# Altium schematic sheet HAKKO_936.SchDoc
size A3; DocumentNumber: 1/1; Revision: 1.0
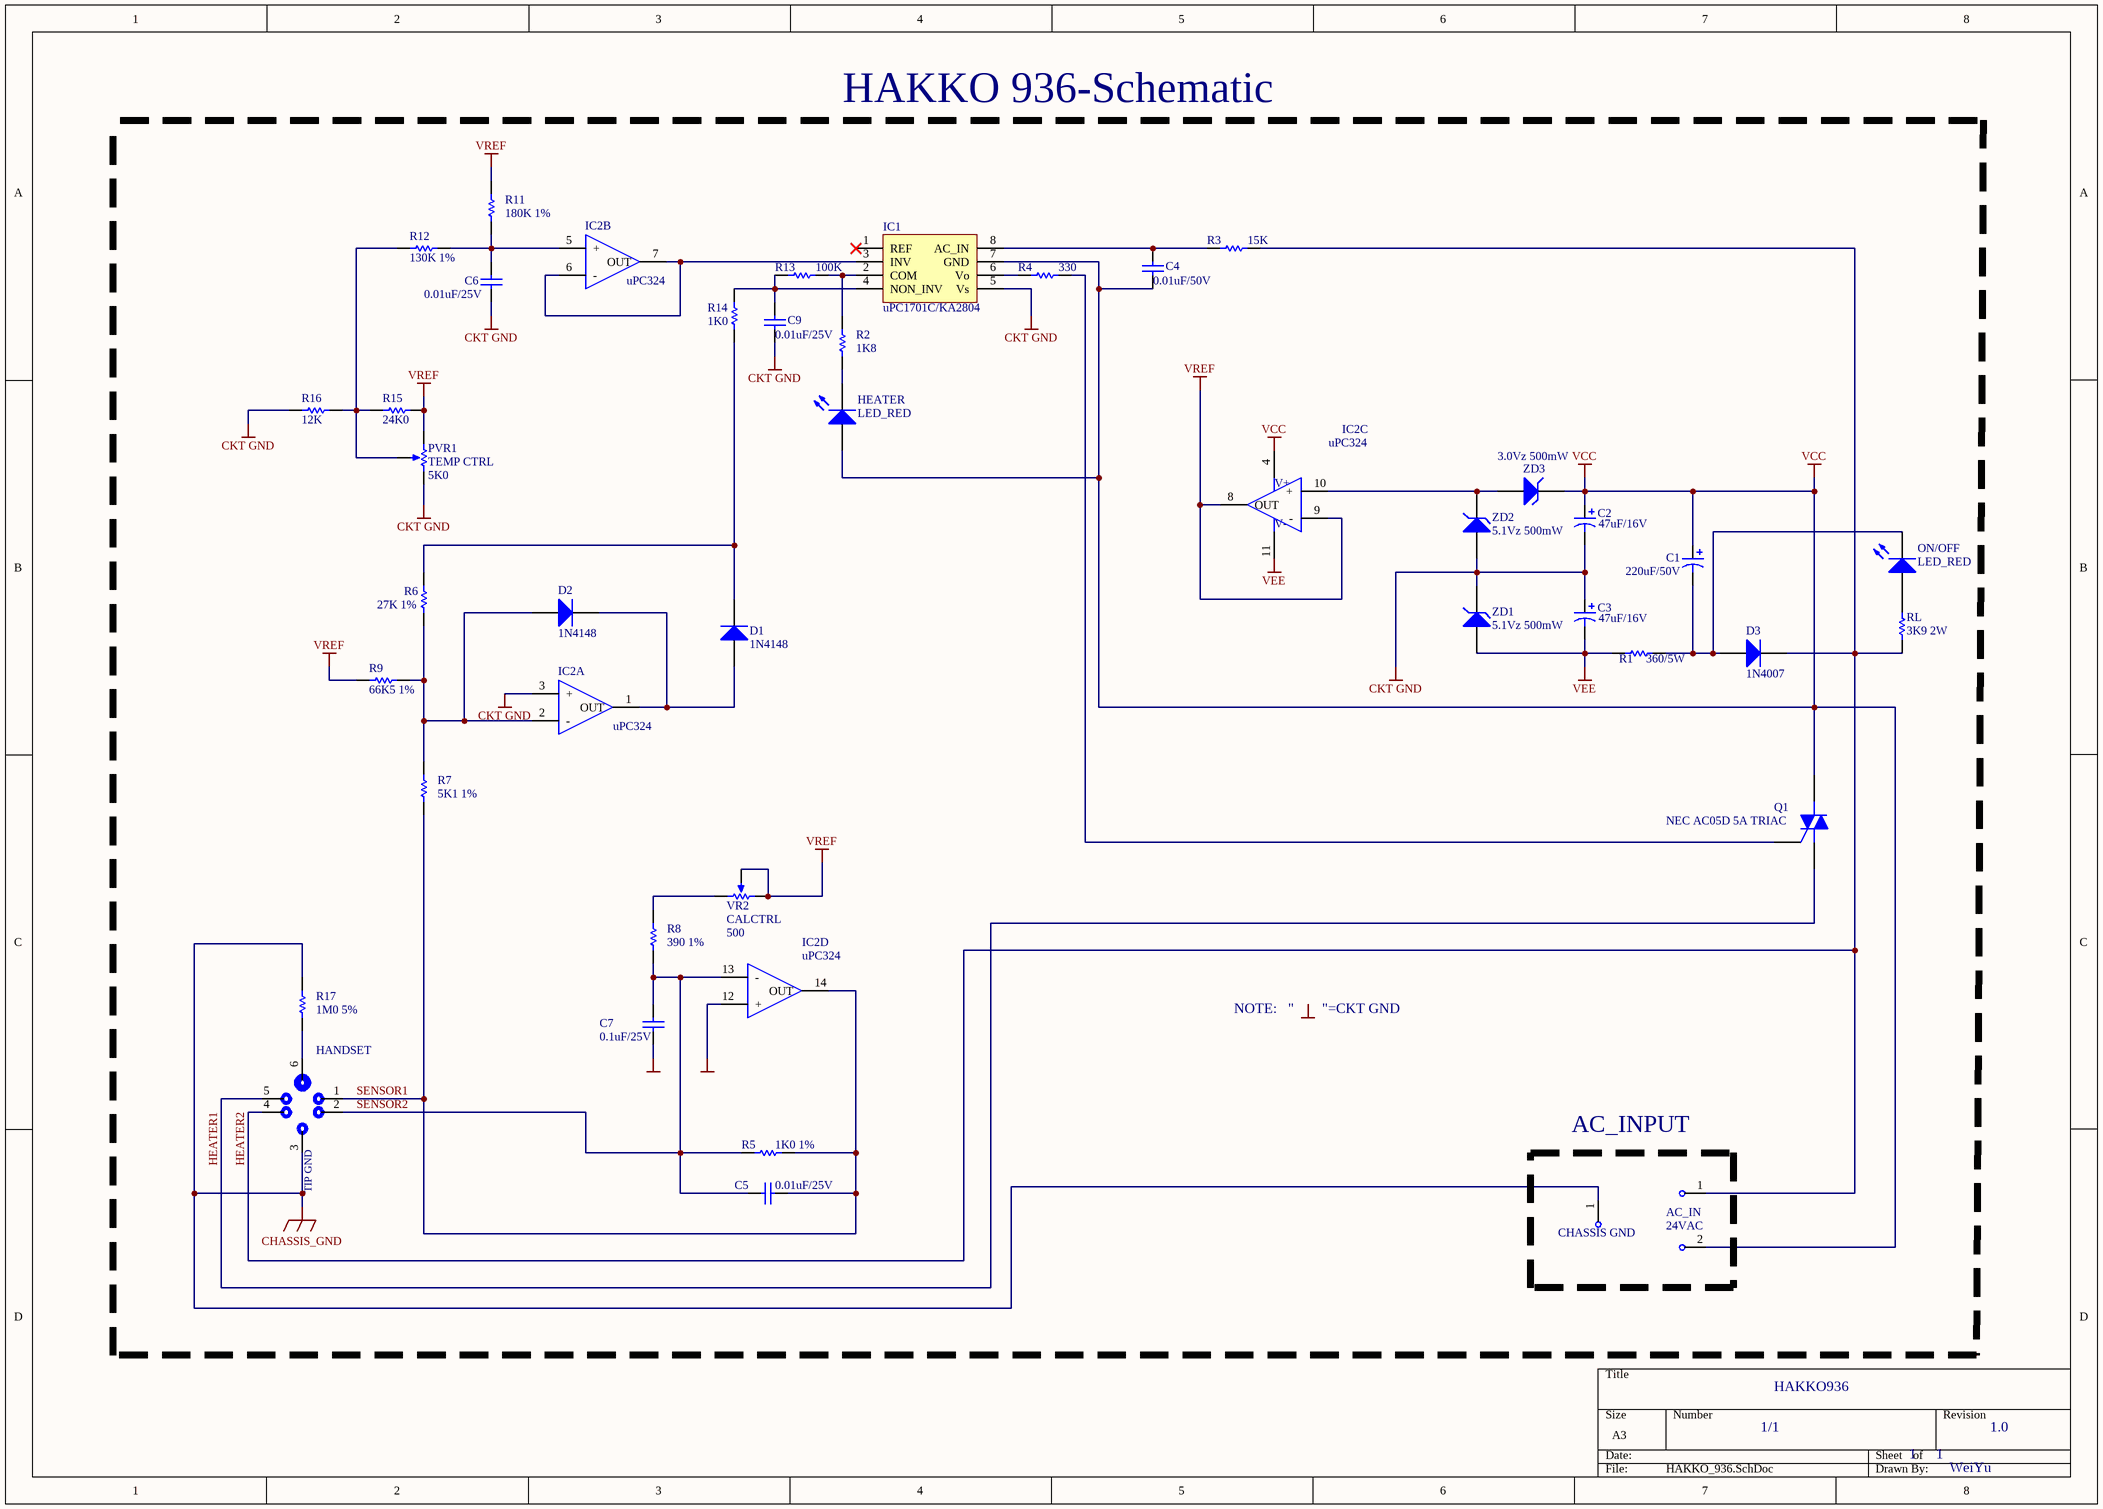
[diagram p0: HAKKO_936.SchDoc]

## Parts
AC_IN  24VAC  [AC_IN]
C1  220uF/50V  [CAP_POL_5mm]
C2  47uF/16V  [CAP_POL_2.5mm]
C3  47uF/16V  [CAP_POL_2.5mm]
C4  0.01uF/50V  [CAP_5.05mm]
C5  0.01uF/25V  [CAP_5.05mm]
C6  0.01uF/25V  [CAP_5.05mm]
C7  0.1uF/25V  [CAP_5.05mm]
C9  0.01uF/25V  [CAP_5.05mm]
CHASSIS_GND  CHASSIS GND  [CHASSIS_GND]  (value not drawn)
D1  1N4148  [DO-41]
D2  1N4148  [DO-41]
D3  1N4007  [DO-41]
HANDSET  HANDSET SOCKET  [HANDSET - metal]  (value not drawn)
HEATER  LED_RED  [LED]
IC1  uPC1701C/KA2804  [uPC1701C]
IC2  uPC324  [UPC324C]  (parts A,B,C,D of 4)
ON/OFF  LED_RED  [LED]
PVR1  TEMP CTRL  value 5K0  [RK09L1140A65]
Q1  NEC AC05D 5A TRIAC  [TRIAC]
R1  360/5W  [RES_2W]
R2  1K8  [RES_1/4W]
R3  15K  [RES_1/4W]
R4  330  [RES_1/4W]
R5  1K0 1%  [RES_1/4W]
R6  27K 1%  [RES_1/4W]
R7  5K1 1%  [RES_1/4W]
R8  390 1%  [RES_1/4W]
R9  66K5 1%  [RES_1/4W]
R11  180K 1%  [RES_1/4W]
R12  130K 1%  [RES_1/4W]
R13  100K  [RES_1/4W]
R14  1K0  [RES_1/4W]
R15  24K0  [RES_1/4W]
R16  12K  [RES_1/4W]
R17  1M0 5%  [RES_1/4W]
RL  3K9 2W  [RES_2W]
VR2  CALCTRL  value 500  [Bournes_3362P]
ZD1  5.1Vz 500mW  [DO-35]
ZD2  5.1Vz 500mW  [DO-35]
ZD3  3.0Vz 500mW  [DO-35]

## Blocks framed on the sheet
AC_INPUT: AC_IN CHASSIS_GND

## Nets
CHASSIS_GND: CHASSIS_GND.1 HANDSET.3 R17.2
CKT GND: C2.2 C3.1 C6.1 C7.1 C9.1 IC1.5(Vs) IC2.3(+) IC2.12(+) PVR1.2(BOT) R16.2 ZD1.K ZD2.A
VCC: AC_IN.2 C1.1 C2.1 C4.1 HEATER.A IC1.7(GND) IC2.4(V+) Q1.T1 ZD3.K
VEE: C3.2 IC2.11(V+) R1.1 ZD1.A
VREF: IC2.8(OUT) IC2.9(-) PVR1.1(TOP) R9.2 R11.2 R15.1 VR2.1(TOP) VR2.3(TAP)
HEATER1: HANDSET.5 Q1.T2
HEATER2: AC_IN.1 D3.K HANDSET.4 R3.2 RL.1
SENSOR1: C5.1 HANDSET.1 IC2.14(OUT) R5.1 R7.1
SENSOR2: C5.2 C7.2 HANDSET.2 IC2.13(-) R5.2 R8.1
NetC1_2: C1.2 D3.A ON/OFF.K R1.2
NetC4_2: C4.2 IC1.8(AC_IN) R3.1
NetC6_2: C6.2 IC2.5(+) R11.1 R12.1
NetC9_2: C9.2 IC1.4(NON_INV) R13.1 R14.2
NetD1_A: D1.A D2.K IC2.1(OUT)
NetD1_K: D1.K R6.2 R14.1
NetD2_A: D2.A IC2.2(-) R6.1 R7.2 R9.1
NetHANDSET_6: HANDSET.6 R17.1
NetHEATER_K: HEATER.K R2.1
NetIC1_2: IC1.2(COM) R2.2 R13.2
NetIC1_3: IC1.3(INV) IC2.6(-) IC2.7(OUT)
NetIC1_6: IC1.6(Vo) R4.1
NetIC2_10: IC2.10(+) ZD2.K ZD3.A
NetON/OFF_A: ON/OFF.A RL.2
NetPVR1_3: PVR1.3(TAP) R12.2 R15.2 R16.1
NetQ1_G: Q1.G R4.2
NetR8_2: R8.2 VR2.2(BOT)

Not connected (* = marked no-connect by the designer): IC1 1(REF)*

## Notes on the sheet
- HAKKO 936-Schematic
- NOTE:
- "
- "=CKT GND
- (near HANDSET) TIP GND
- 1
- WeiYu

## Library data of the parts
AC_IN = 24VAC_IN: POWER
C1-C3 = Cap Pol1: Polarized Capacitor (Radial)
C4-C7 C9 = Cap: Capacitor
D1-D3 = Diode: Default Diode
HEATER ON/OFF = LED1: Typical RED GaAs LED
IC1 = uPC1701C: TRIAC DRIVER
IC2 = uPC324: Quar Amplifier
PVR1 VR2 = RPot: Potentiometer; Sim Note: Enter the Resistance value and the set point into parameter fields.; Set Position: 0.5
Q1 = Triac: Silicon Bidirectional Triode Thyristor; Note: Pin 2 is electrically connected to Pin 4 (TAB)
R1-R9 R11-R17 RL = Res Semi: Semiconductor Resistor
ZD1-ZD3 = D Zener: Zener Diode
